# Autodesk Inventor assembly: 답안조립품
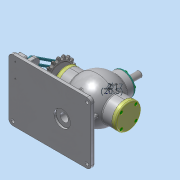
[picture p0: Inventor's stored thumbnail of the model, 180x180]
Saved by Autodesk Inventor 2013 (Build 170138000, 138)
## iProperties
Created: 2017-07
Part Number: 답안조립품
Document SubType Name: Assembly
Designer: dgall
Mass: 3277.47 g
Surface Area: 2432.27 cm^2
Volume: 944.512 cm^3
Density: 3.47001 g/cm^3
Author: dgall
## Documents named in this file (20)
- C:\Users\dgall\Desktop\370707V1018\답안조립품.iam
- C:\Users\dgall\Desktop\370707V1018\본체.ipt
- C:\Users\dgall\Desktop\370707V1018\본체커버.ipt
- C:\Users\dgall\Desktop\370707V1018\베어링 6202.ipt
- C:\Users\dgall\Desktop\370707V1018\앞커버.ipt
- C:\Users\dgall\Desktop\370707V1018\뒤커버.ipt
- C:\Users\dgall\Desktop\370707V1018\슬라이드 커버.ipt
- C:\Users\dgall\Desktop\370707V1018\축.ipt
- C:\Users\dgall\Desktop\370707V1018\오일실.ipt
- C:\Users\dgall\Desktop\370707V1018\와셔 8x17.ipt
- C:\Users\dgall\Desktop\370707V1018\너트 M8x1.ipt
- C:\Users\dgall\Desktop\370707V1018\볼트 M4x12.ipt
- C:\Users\dgall\Desktop\370707V1018\슬라이드.ipt
- C:\Users\dgall\Desktop\370707V1018\키 3 x 3 x 12.ipt
- C:\Users\dgall\Desktop\370707V1018\스프로킷.ipt
- C:\Users\dgall\Desktop\370707V1018\고정핀.ipt
- C:\Users\dgall\Desktop\370707V1018\연결대.ipt
- C:\Users\dgall\Desktop\370707V1018\와셔 ISO 7093 A.ipt
- C:\Users\dgall\Desktop\370707V1018\둥근머리 볼트 M4x8.ipt
- C:\Users\dgall\Desktop\370707V1018\스프링.ipt
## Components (1 placed, 1 different names)
1. 고정핀:1
